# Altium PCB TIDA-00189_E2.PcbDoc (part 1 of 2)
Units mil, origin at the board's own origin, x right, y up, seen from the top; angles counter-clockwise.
Board outline 2350 x 1950 mil, 4 copper layers (Layer 1 - Top Layer, Layer 2 - GND, Layer 3 - Inner Layer, Layer 4 - Bottom Layer), stack 61.4 mil thick; 163 components, 96 nets, 412 pads, 169 vias.
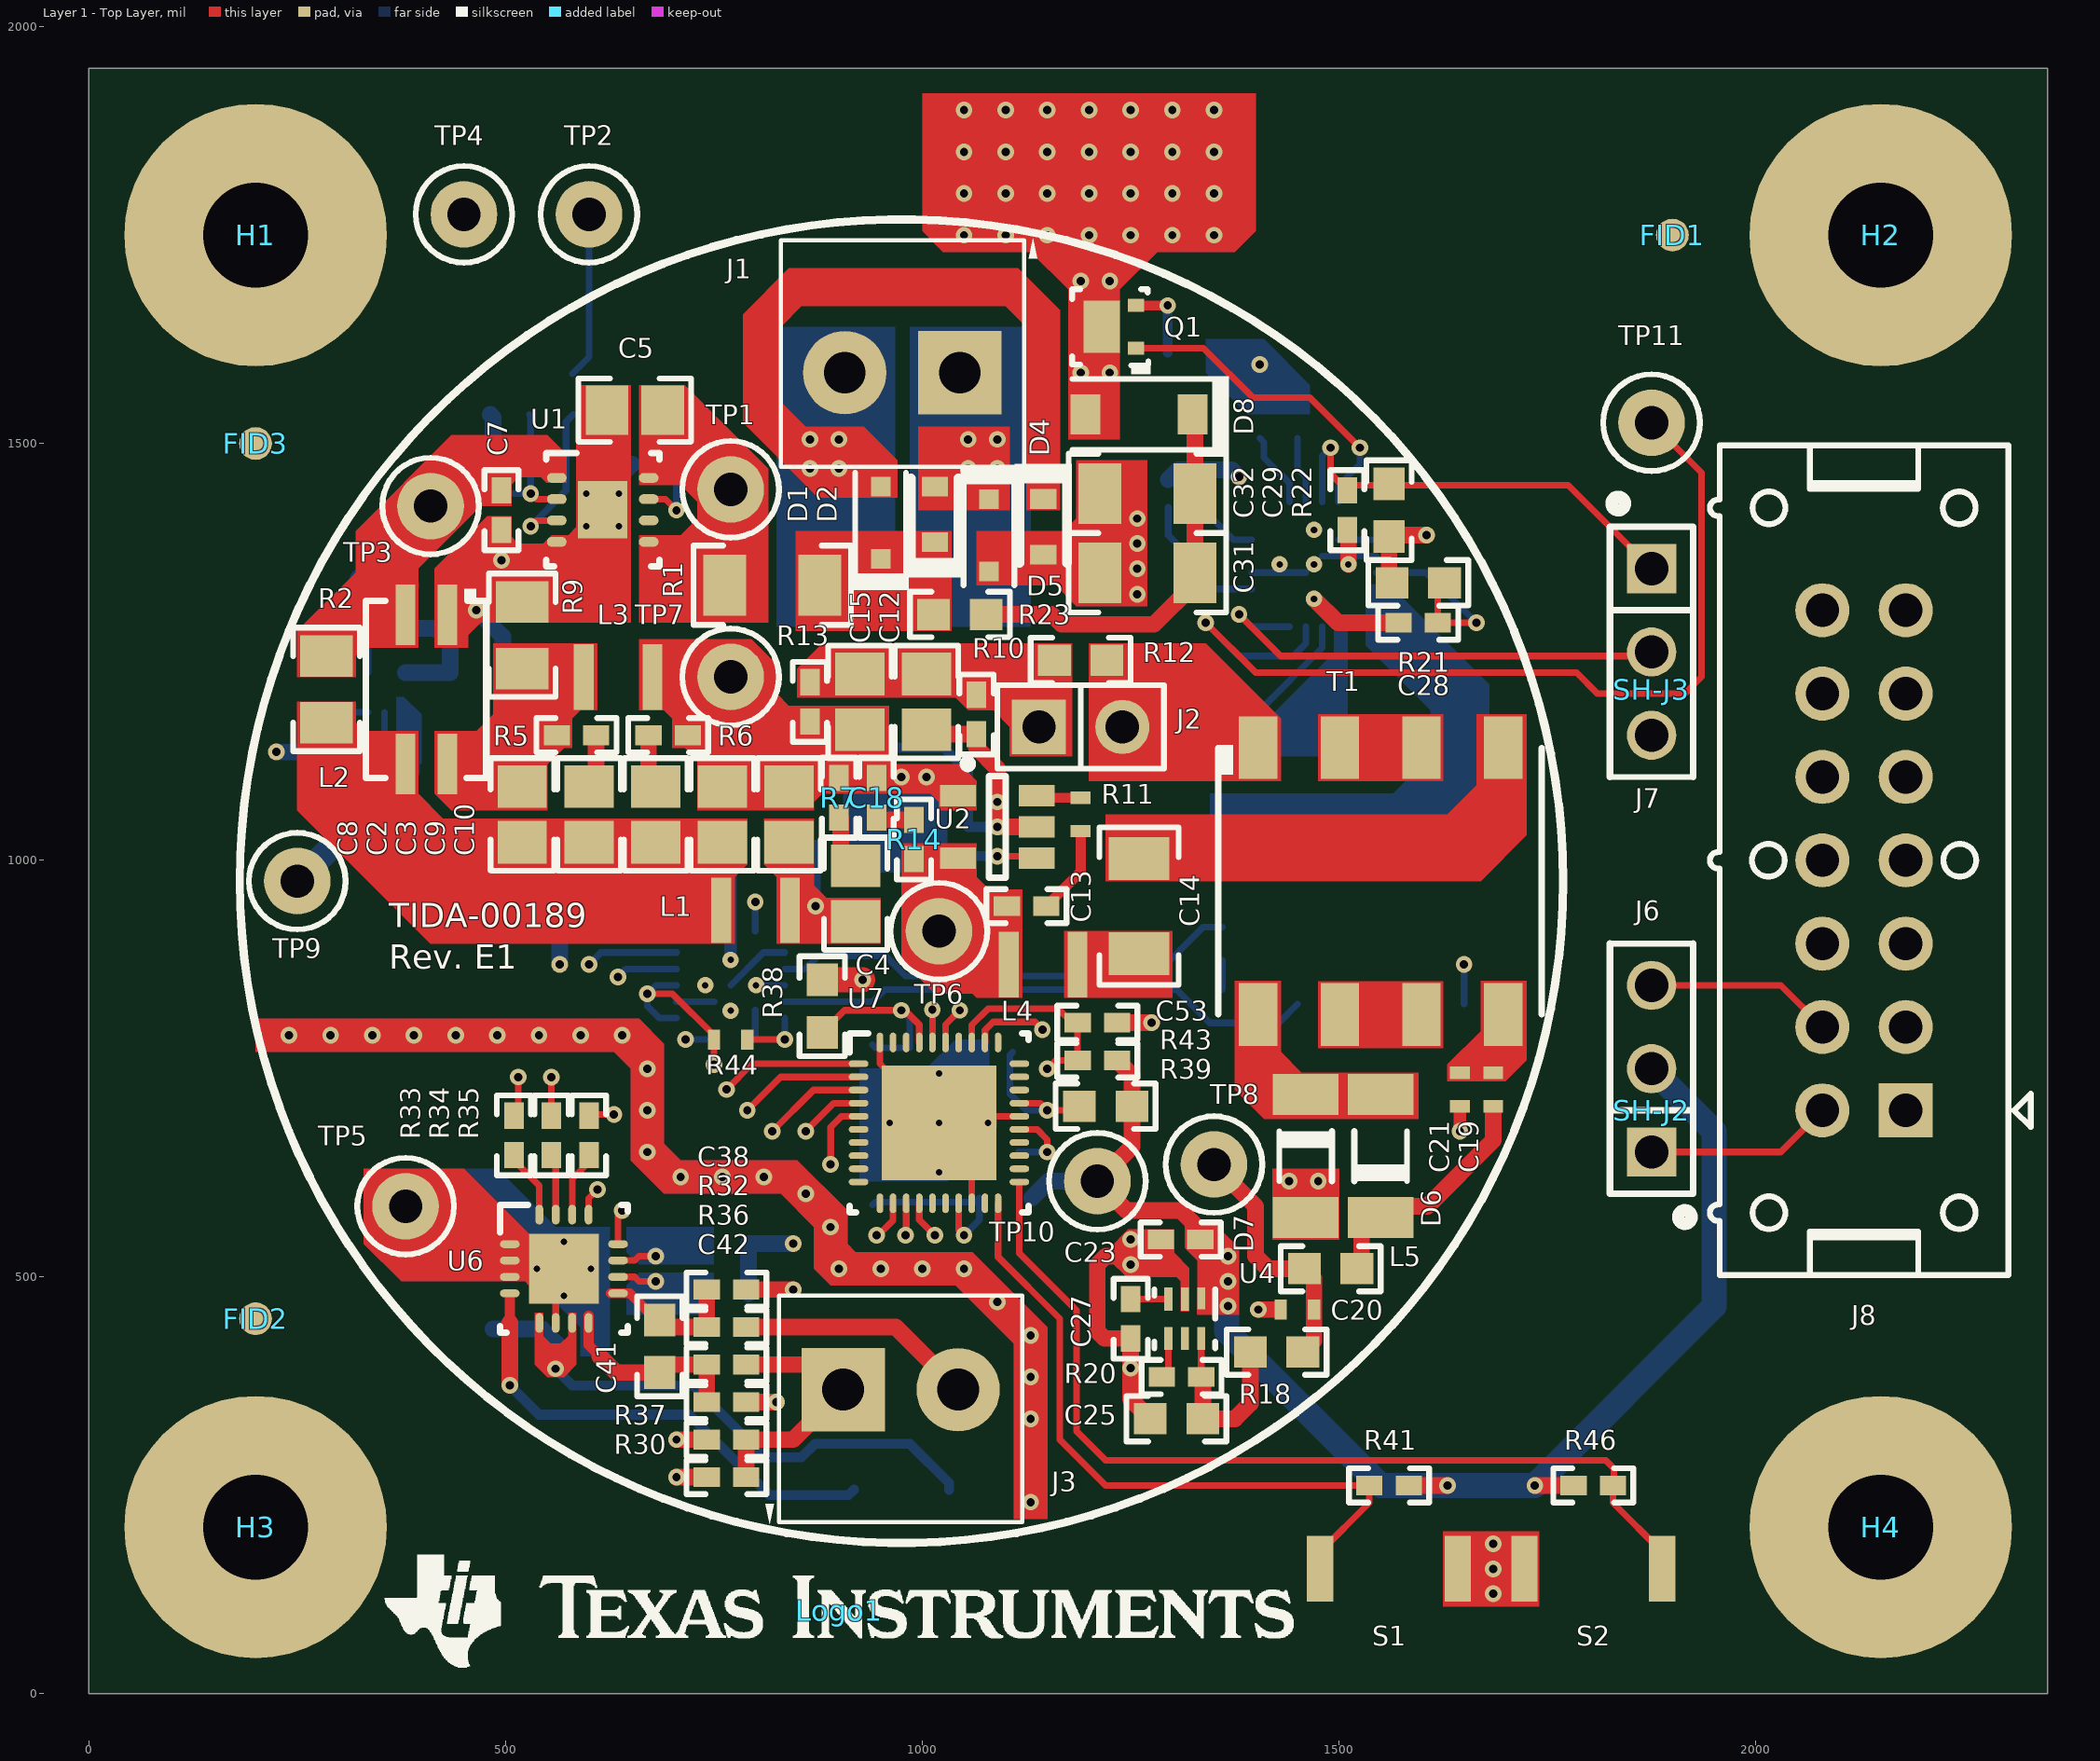
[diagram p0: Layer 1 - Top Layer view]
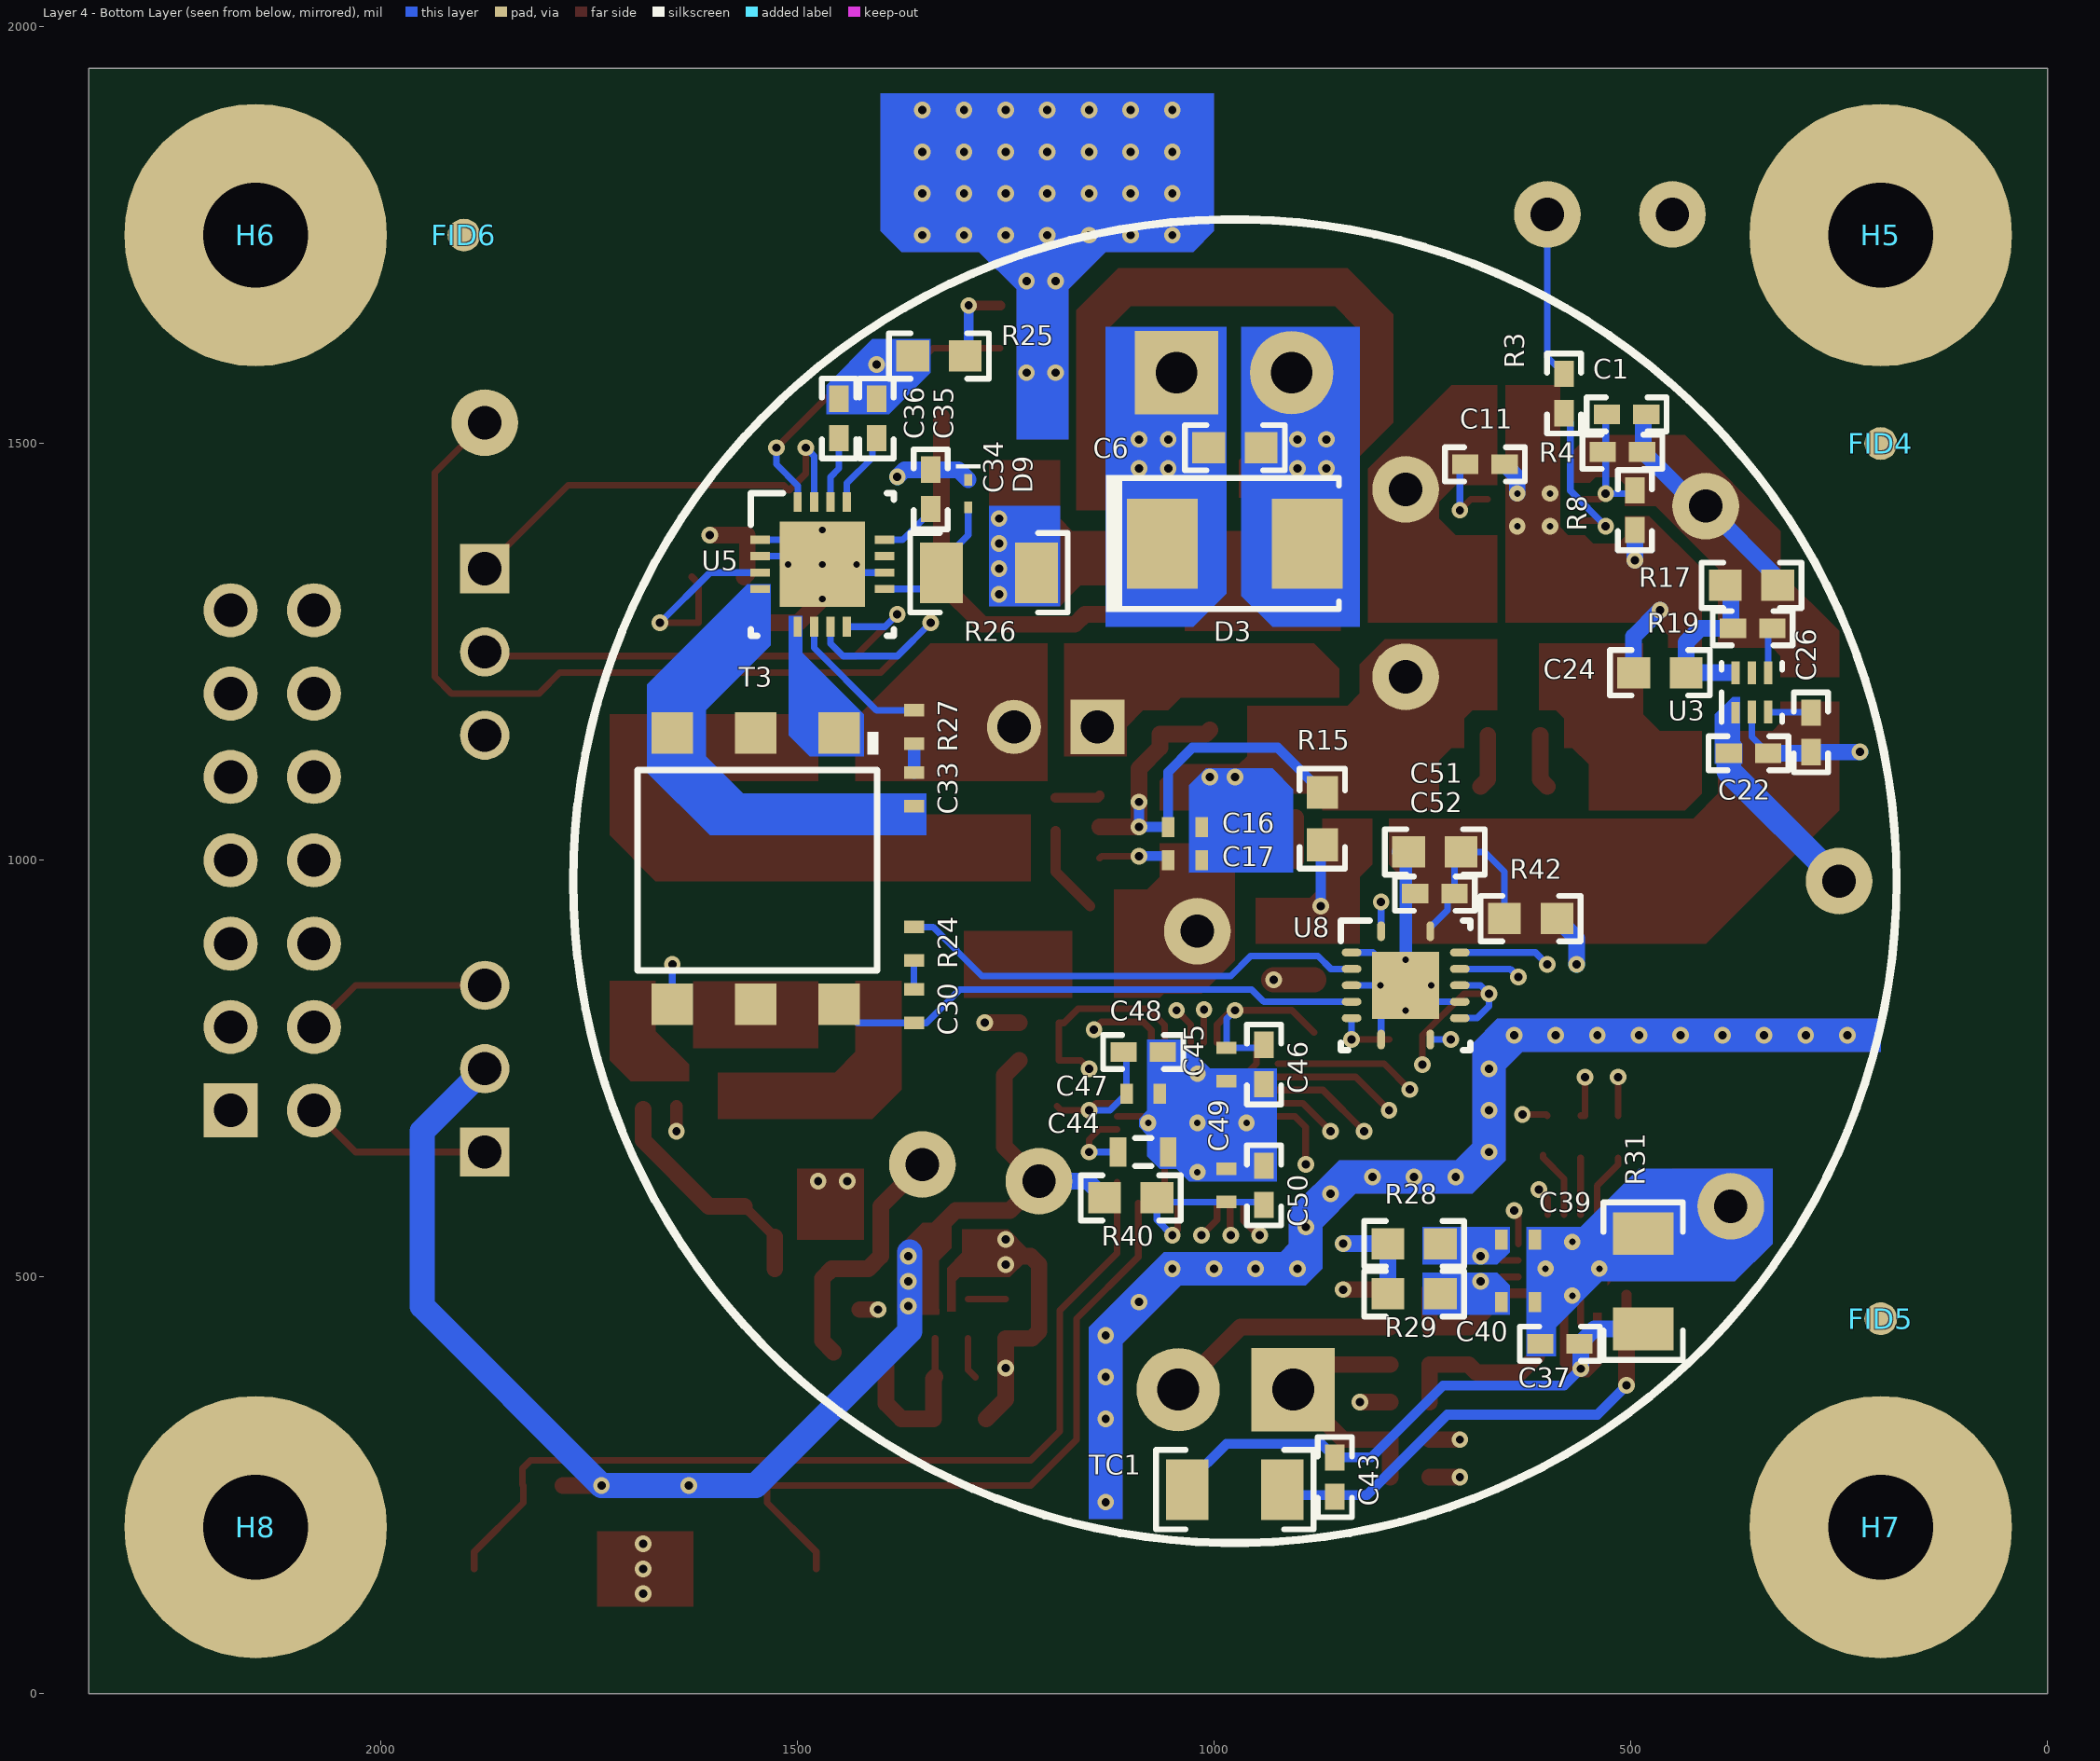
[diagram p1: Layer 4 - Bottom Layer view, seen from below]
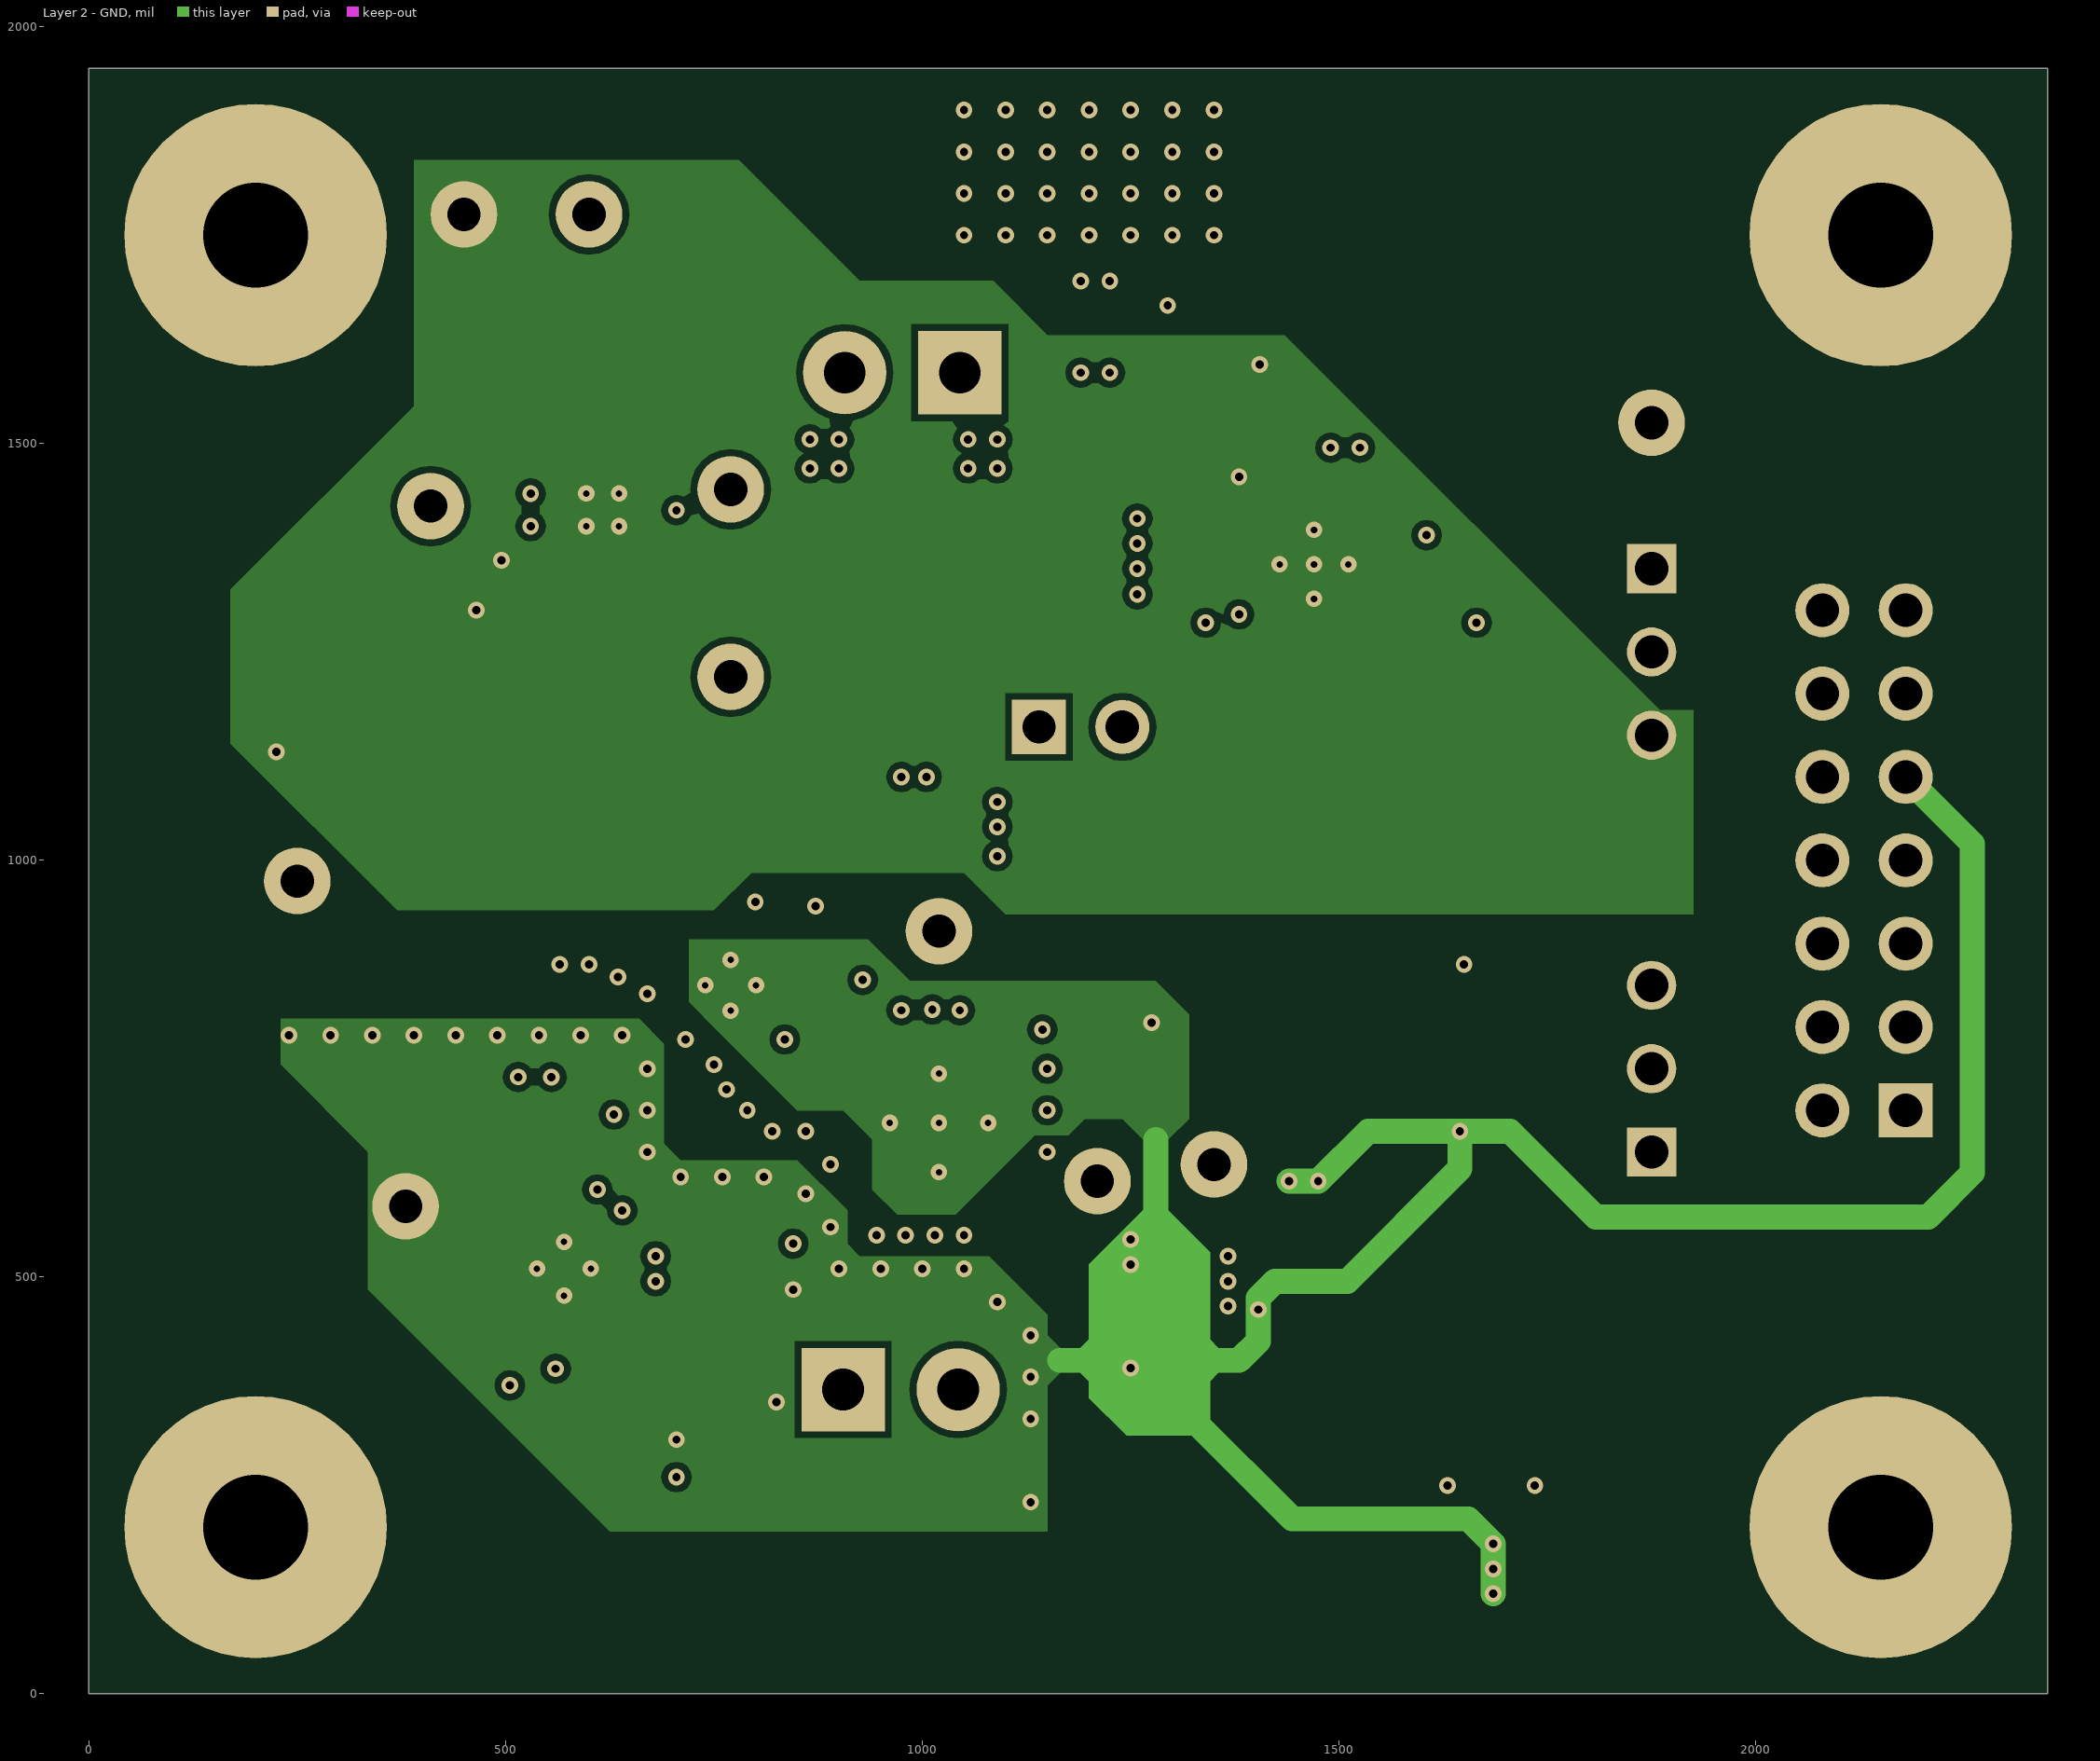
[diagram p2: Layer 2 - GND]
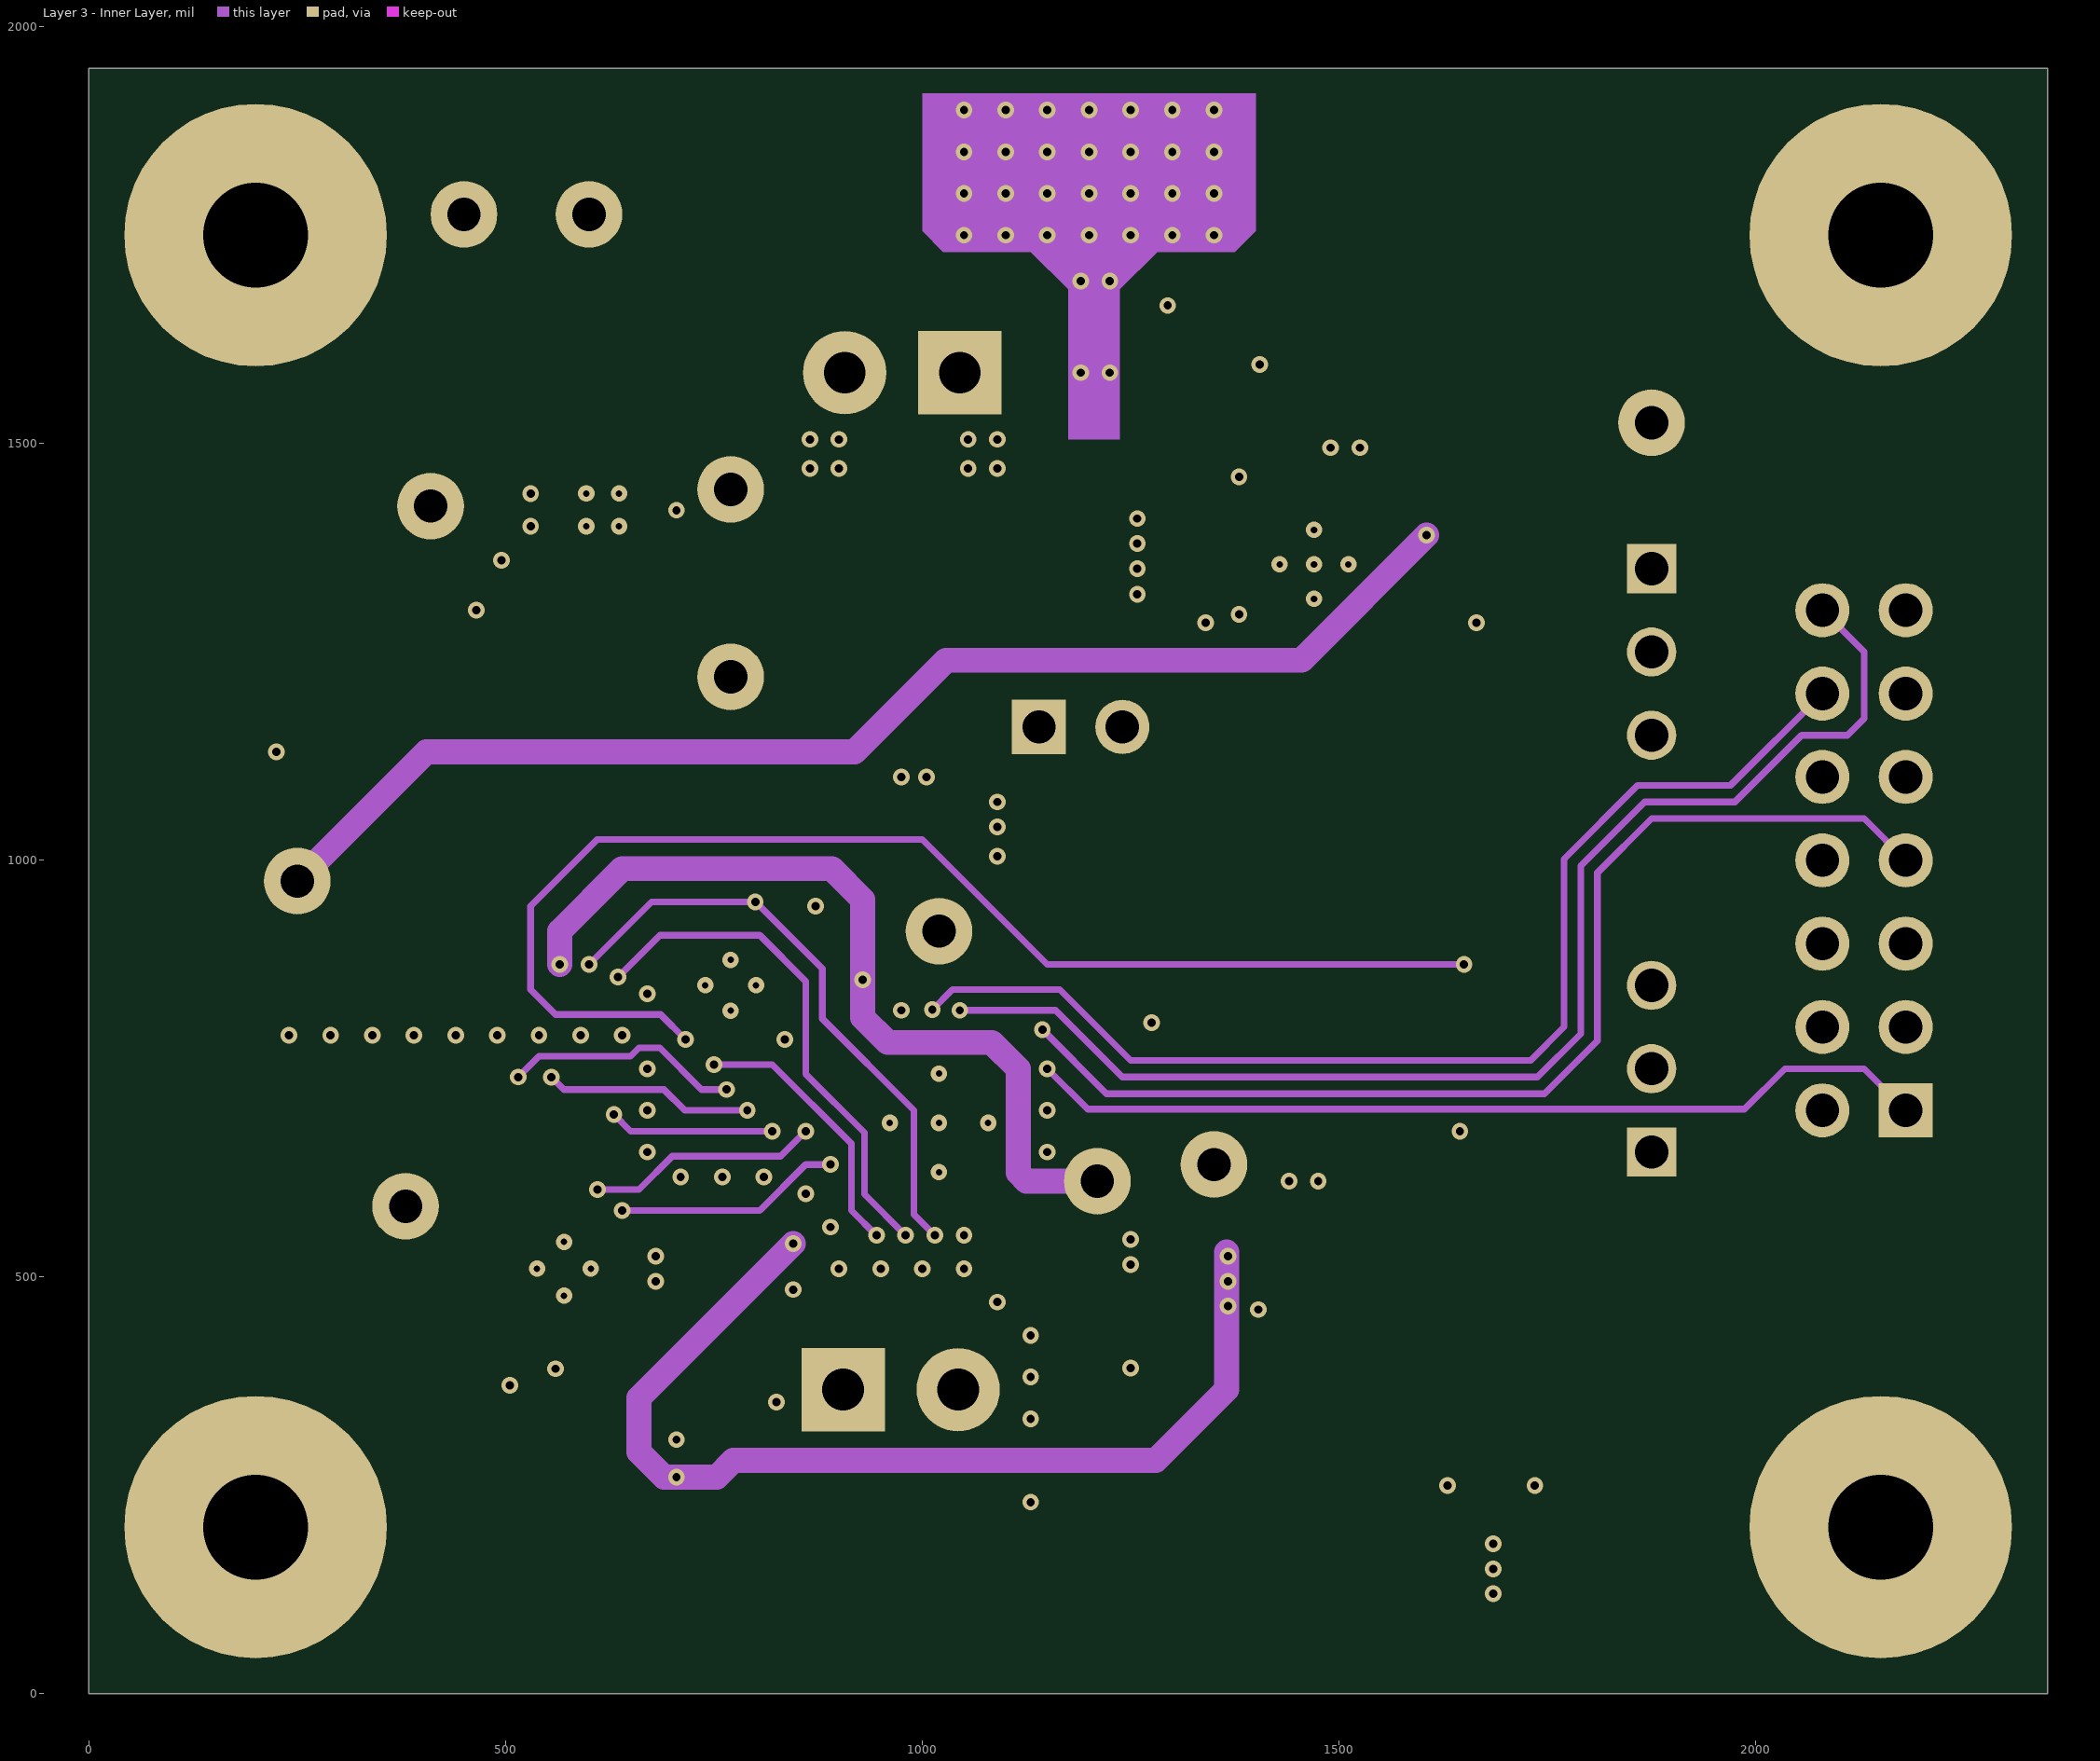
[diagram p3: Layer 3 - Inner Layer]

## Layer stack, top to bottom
Layer 1 - Top Layer: signal copper 1.4
Dielectric: core 18.6, 370HR, Dk 4.8
Layer 2 - GND: signal copper 1.4
Dielectric: prepreg 18.6, 370HR, Dk 4.8
Layer 3 - Inner Layer: signal copper 1.4
Dielectric: core 18.6, 370HR, Dk 4.8
Layer 4 - Bottom Layer: signal copper 1.4

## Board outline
0,0 0,1950 2350,1950 2350,0

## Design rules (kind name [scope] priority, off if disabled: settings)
AcuteAngle [All] p1: minimum=4.50000000000000E+0001 checktracksonly=FALSE
AssemblyTestPointUsage [All] p1: valid=2
Clearance Clearance_U7 [InComponent('U7')] p1: gap=7
Clearance Clearance_BoardEdge_MountingHoles [OnCopper and InComponentClass('Mounting Holes') vs IsKeepOut] p2: gap=40
Clearance Clearance_BoardEdge_Poly [OnCopper and InPoly vs IsKeepOut] p3: gap=25
Clearance Clearance_BoardEdge [OnCopper and Not InComponentClass('Logo') and not InComponentClass('FiducialMark') and not InRegion(1000,500,4000,800) and Not IsKeepout vs IsKeepOut] p4: gap=75
Clearance Clearance_Poly [InPolygon] p5: gap=8
Clearance [All] p6: gap=7.5
ComponentClearance ComponentClearance_Shunt [InComponentClass('Header') vs InComponentClass('Shunt')] p1 off: gap=0 collisioncheckmode=3 verticalgap=0 showdistances=FALSE
ComponentClearance ComponentClearance_Logo [InComponentClass('Logo')] p2 off: gap=50 collisioncheckmode=3 verticalgap=10 showdistances=FALSE
ComponentClearance ComponentClearance_ScrewToNut [(HasFootprint('NY PMS 440 0025 PH')) vs (HasFootprint('Keystone_1902C'))] p3 off: gap=5 collisioncheckmode=3 verticalgap=10 showdistances=FALSE
ComponentClearance ComponentClearance_MountingHoles [InComponentClass('Mounting Holes')] p4 off: gap=250 collisioncheckmode=3 verticalgap=100000 showdistances=FALSE
ComponentClearance ComponentClearance_SmallPassives [HasFootprint('0201*') or HasFootprint('0402*') or HasFootprint('0508') or HasFootprint('0603*') or HasFootprint('0612') or HasFootprint('0805*') or HasFootprint('0815*') or HasFootprint('0830*') or HasFootprint('1206*') or HasFootprint('1210*') or HasFootprint('1808*') or HasFootprint('1812*') or HasFootprint('1825*') or HasFootprint('2010*') or HasFootprint('2220*') or HasFootprint('2225*') or HasFootprint('2512*') or HasFootprint('2728*') or HasFootprint('3518*') vs HasFootprint('0201*') or HasFootprint('0402*') or HasFootprint('0508') or HasFootprint('0603*') or HasFootprint('0612') or HasFootprint('0805*') or HasFootprint('0815*') or HasFootprint('0830*') or HasFootprint('1206*') or HasFootprint('1210*') or HasFootprint('1808*') or HasFootprint('1812*') or HasFootprint('1825*') or HasFootprint('2010*') or HasFootprint('2220*') or HasFootprint('2225*') or HasFootprint('2512*') or HasFootprint('2728*') or HasFootprint('3518*')] p5 off: gap=20 collisioncheckmode=3 verticalgap=10 showdistances=FALSE
ComponentClearance ComponentClearance_THtoSMT [IsThruComponent vs IsSMTComponent] p6 off: gap=100 collisioncheckmode=3 verticalgap=30 showdistances=FALSE
ComponentClearance ComponentClearance_THtoTH [IsThruComponent vs IsThruComponent] p7 off: gap=118.11 collisioncheckmode=3 verticalgap=30 showdistances=FALSE
ComponentClearance [All] p8 off: gap=40 collisioncheckmode=3 verticalgap=10 showdistances=FALSE
DiffPairsRouting [All] p1: maxlimit=100 minlimit=10 mostfreqgap=10 maxuncoupledlength=1000
FabricationTestPointUsage TestPointUsage [All] p1: valid=2 allowmultiple=FALSE
FabricationTestpoint Testpoint [All] p1: side=3 testpointundercomponent=TRUE minsize=40 maxsize=100 preferedsize=60 minholesize=0 maxholesize=40 preferedholesize=32 testpointgrid=1 allowsidetop=TRUE allowsidebottom=TRUE usegrid=TRUE gridtolerance=0.01
FanoutControl Fanout_LCC [IsLCC] p1: bgadir=Out bgaviamode=Centered fanoutstyle=Auto fanoutdirection=Alternating viagrid=1 // Fanout_LCC (Default Rule)
FanoutControl Fanout_BGA [IsBGA] p2: bgadir=Out bgaviamode=Centered fanoutstyle=Auto fanoutdirection=Alternating viagrid=1 // Fanout_BGA (Default Rule)
FanoutControl Fanout_Default [All] p4: bgadir=Out bgaviamode=Centered fanoutstyle=Auto fanoutdirection=Alternating viagrid=1 // Fanout_Default (Default Rule)
FanoutControl Fanout_Small [(CompPinCount < 5)] p5: bgadir=Out bgaviamode=Centered fanoutstyle=Auto fanoutdirection=OutThenIn viagrid=1 // Fanout_Small (Default Rule)
HoleSize [All] p1: absolutevalues=TRUE maxlimit=251 minlimit=7.8 maxpercent=80.000 minpercent=20.000
MinimumAnnularRing MinimumAnnularRing_ThermalPadVias [IsVia and InAnyComponent] p1: minimumring=5.91
MinimumAnnularRing [All] p2: minimumring=5
MinimumSolderMaskSliver MinimumSolderMaskSliver_Logo [InComponentClass('Logo') vs InComponentClass('Logo')] p1: minsoldermaskwidth=0.7
MinimumSolderMaskSliver [All] p2: minsoldermaskwidth=3.94
PlaneConnect [All] p1: planeconnectstyle=Direct reliefexpansion=10 reliefentries=4 reliefconductorwidth=10 reliefairgap=10
PolygonConnect [All] p1: connectstyle=Direct reliefconductorwidth=10 reliefentries=4 polygonreliefangle="90 Angle" airgapwidth=10
RoutingVias ThermalPadVias [IsVia and InAnyComponent] p1: holewidth=7.87 width=19.68 viastyle="Through Hole" minholewidth=7.87 minwidth=19.68 maxholewidth=12.99 maxwidth=23.62
RoutingVias [All] p2: holewidth=16 width=34 viastyle="Through Hole" minholewidth=7.87 minwidth=20 maxholewidth=40 maxwidth=65
SMDToCorner [All] p1: distance=30000
SilkToSilkClearance [All] p1 off: silktosilkclearance=5
SilkscreenOverComponentPads [All] p1: minsilkscreentomaskgap=2
SolderMaskExpansion [All] p1: expansion=1.97
Width [All] p1: maxlimit=100 minlimit=6 preferedwidth=10 checkconnectedcopper=TRUE
14 further rules are at their usual default settings.

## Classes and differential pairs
component class TIDA-00189_E2_PWR: C1 C2 C3 C4 C5 C6 C7 C8 C9 C10 C11 C12 C13 C14 C15 C16 C17 C18 C19 C20 C21 C22 C23 C24 C25 C26 C27 D1 D2 D3 D4 D5 D6 D7 J1 J2 L1 L2 L3 L4 L5 R1 R2 R3 R4 R5 R6 R7 R8 R9 R10 R11 R12 R13 R14 R15 R17 R18 R19 R20 T1 TP1 TP2 TP3 TP4 TP5 TP6 TP7 TP8 TP9 TP10 U1 U2 U3 U4
component class TIDA-00189_E2_Periph: J6 J7 J8 R46 S2 SH-J2 SH-J3
component class TIDA-00189_E2_DAC: C28 C29 C30 C31 C32 C33 C34 C35 C36 D8 D9 Q1 R21 R22 R23 R24 R25 R26 R27 T3 TP11 U5
component class TIDA-00189_E2_AFE_MCU: C37 C38 C39 C40 C41 C42 C43 C44 C45 C46 C47 C48 C49 C50 C51 C52 C53 J3 R28 R29 R30 R31 R32 R33 R34 R35 R36 R37 R38 R39 R40 R41 R42 R43 R44 S1 TC1 U6 U7 U8
component class Shunt: SH-J2 SH-J3
component class "Mounting Holes": H1 H2 H3 H4
component class Logo: Logo1
component class TIDA-00189_E2_Hardware: FID1 FID2 FID3 FID4 FID5 FID6 H1 H2 H3 H4 H5 H6 H7 H8 Logo1 ZZ1 ZZ2 ZZ3 ZZ4
component class FiducialMark: FID1 FID2 FID3 FID4 FID5 FID6
component class AssemblyNote: ZZ1 ZZ2 ZZ3 ZZ4

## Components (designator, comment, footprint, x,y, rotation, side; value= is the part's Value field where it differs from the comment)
C1 "CAP, CERM, 0.01uF, 10V, +/-10%, X5R, 0402" 0402 505,1535 r0 bottom
C2 "GRM21BR71A106KE51L" 0805 600,1055 r90 top
C3 "GRM21BR71A106KE51L" 0805 680,1055 r90 top
C4 "GRM21BR71A106KE51L" 0805 920,960 r90 top
C5 "CAP, CERM, 0.47uF, 100V, +/-10%, X7R, 0805" 0805 655,1540 r180 top
C6 "CAP, CERM, 0.01uF, 100V, +/-10%, X7R, 0603" 0603 975,1495 r0 bottom locked
C7 "CAP, CERM, 2.2uF, 16V, +/-10%, X5R, 0402" 0402 495,1420 r270 top
C8 "CAP, CERM, 10uF, 10V, +/-10%, X7R, 0805" 0805 520,1055 r90 top
C9 "GRM21BR71A106KE51L" 0805 760,1055 r90 top
C10 "GRM21BR71A106KE51L" 0805 840,1055 r90 top
C11 "GRM155R61A104KA01D" 0402 675,1475 r180 bottom
C12 "CAP, CERM, 10uF, 10V, +/-10%, X7R, 0805" 0805 1005,1190 r90 top
C13 "CAP, CERM, 1uF, 10V, +/-10%, X5R, 0402" 0402 1125,945 r180 top
C14 "CAP, CERM, 22uF, 10V, +/-10%, X5R, 1206" 1206 1260,945 r270 top
C15 "CAP, CERM, 10uF, 10V, +/-10%, X7R, 0805" 0805 925,1190 r270 top
C16 "CAP, CERM, 4.7uF, 10V, +/-20%, X5R, 0402" 0402S 1035,1040 r180 bottom
C17 "CAP, CERM, 4.7uF, 10V, +/-20%, X5R, 0402" 0402S 1035,1000 r180 bottom
C18 "GRM155R71H561KA01D" 0402 945,1075 r90 top
C19 "CAP, CERM, 1uF, 10V, +/-10%, X5R, 0402" 0402S 1685,725 r90 top
C20 "CAP, CERM, 1uF, 10V, +/-10%, X5R, 0402" 0402S 1450,461 r180 top
C21 "CAP, CERM, 1uF, 10V, +/-10%, X5R, 0402" 0402S 1645,725 r270 top
C22 "CAP, CERM, 1uF, 10V, +/-10%, X5R, 0402" 0402 358.7,1128.38 r180 bottom
C23 "GRM155R61A105KE15D" 0402 1310,545 r180 top
C24 "GRM188R71A225KE15D" 0603 465,1225 r0 bottom
C25 "GRM188R71A225KE15D" 0603 1305,330 r180 top
C26 "CAP, CERM, 0.1uF, 6.3V, +/-10%, X7R, 0402" 0402 283.7,1153.38 r270 bottom
C27 "GRM155R70J104KA01D" 0402 1250,450 r270 top
C28 "GRM155R71C104KA88D" 0402 1595,1285 r180 top
C29 "GRM155R71C104KA88D" 0402 1510,1420 r270 top
C30 "GRM155R71C102KA01D" 0402S 1360,825 r90 bottom
C31 "12061C104JAT2A" 1206 1270,1345 r180 top
C32 "GRM31CR72A105KA01L" 1206 1270,1440 r180 top
C33 "GRM155R71C102KA01D" 0402S 1360,1085 r270 bottom
C34 "GRM155R70J222KA01D" 0402 1340,1445 r90 bottom
C35 "GRM155R70J222KA01D" 0402 1405,1530 r90 bottom
C36 "GRM155R70J222KA01D" 0402 1450,1530 r90 bottom
C37 "GRM155R61A105KE15D" 0402 585,420 r180 bottom
C38 "GRM155R60J274KE01D" 0402 765,485 r180 top
C39 "GRM155R60J224KE01D" 0402S 635,545 r180 bottom
C40 "GRM155R60J224KE01D" 0402S 635,470 r180 bottom
C41 "GRM188R60J475KE19D" 0603 685,417 r270 top
C42 "GRM155R60J274KE01D" 0402 765,350 r0 top
C43 "GRM155R61A105KE15D" 0402 855,260 r270 bottom
C44 "GRM188R70J474KA01D" 0603S 1085,650 r180 bottom
C45 "GRM155R70J104KA01D" 0402S 985,755 r270 bottom
C46 "CL05A106MQ5NUNC" 0402 940,755 r270 bottom
C47 "GRM155R70J104KA01D" 0402S 1085,720 r180 bottom
C48 "CL05A106MQ5NUNC" 0402 1085,770 r180 bottom
C49 "GRM155R70J104KA01D" 0402S 985,610 r90 bottom
C50 "CL05A106MQ5NUNC" 0402 940,610 r90 bottom
C51 "GRM188R61A335KE15D" 0603 735,1010 r0 bottom
C52 "GRM155R61A104KA01D" 0402 735,960 r0 bottom
C53 "GRM155R70J222KA01D" 0402 1210,805 r0 top
D1 "BAT46WJ,115" SOD-323F 950,1405 r90 top
D2 "CDSU101A" SOD-523F 1015,1415 r90 top
D3 "SM6T39CA" SMB 975,1380 r180 bottom locked
D4 "CDSU101A" SOD-523F 1145,1400 r270 top
D5 "BAT46WJ,115" SOD-323F 1080,1390 r270 top
D6 "PMLL4153,115" SOD-80 1550,645 r90 top
D7 "PMLL4153,115" SOD-80 1460,645 r270 top
D8 "MMSZ4686T1G" SOD-123 1260,1535 r180 top
D9 "ESD9R3.3ST5G" ESD9R3.3ST5G 1295,1440 r270 bottom
FID1 "Fiducial" Fiducial10-30 1900,1750 r0 top
FID2 "Fiducial" Fiducial10-30 200,450 r0 top
FID3 "Fiducial" Fiducial10-30 200,1500 r0 top
FID4 "Fiducial" Fiducial10-30 200,1500 r180 bottom
FID5 "Fiducial" Fiducial10-30 200,450 r180 bottom
FID6 "Fiducial" Fiducial10-30 1900,1750 r180 bottom
H1 "NY PMS 440 0025 PH" "NY PMS 440 0025 PH" 200,1750 r0 top locked
H2 "NY PMS 440 0025 PH" "NY PMS 440 0025 PH" 2150,1750 r0 top locked
H3 "NY PMS 440 0025 PH" "NY PMS 440 0025 PH" 200,200 r0 top locked
H4 "NY PMS 440 0025 PH" "NY PMS 440 0025 PH" 2150,200 r0 top locked
H5 "1902C" Keystone_1902C 200,1750 r180 bottom locked
H6 "1902C" Keystone_1902C 2150,1750 r180 bottom locked
H7 "1902C" Keystone_1902C 200,200 r180 bottom locked
H8 "1902C" Keystone_1902C 2150,200 r180 bottom locked
J1 "ED555/2DS" TERM_BLK_ED555-2DS 1045,1585 r180 top locked
J2 "90120-0122" CONN_90120-0122 1190,1160 r0 top
J3 "ED555/2DS" TERM_BLK_ED555-2DS 905,365 r0 top locked
J6 "PEC03SAAN" CONN_PEC03SAAN 1875,750 r90 top
J7 "PEC03SAAN" CONN_PEC03SAAN 1875,1250 r270 top
J8 "SBH11-PBPC-D07-ST-BK" CONN_SBH11-PBPC-D07-ST-BK 2130,1000 r90 top
L1 "CB2518T470K" IND_CB2518 800,940 r0 top
L2 "DR221-474AE" Bourns_DR221 405,1205 r270 top
L3 "CB2518T470K" IND_CB2518 635,1220 r0 top
L4 "CB2518T330K" IND_CB2518 1145,875 r0 top
L5 "BLM18HG601SN1D" 0603 1490,510 r180 top
Logo1 "Texas Instruments" TI_Horizontal_Overlay_Small 900,100 r0 top
Q1 "BC56-16PA,115" SOT1061 1225,1640 r180 top
R1 "CRCW1206200RFKEA" 1206 820,1330 r180 top
R2 "CRCW08050000Z0EA" 0805_HV 285,1205 r270 top
R3 "CRCW0402100KFKED" 0402 580,1560 r90 bottom
R4 "RES, 698k ohm, 1%, 0.063W, 0402" 0402 510,1490 r180 bottom
R5 "RES, 200 ohm, 1%, 0.063W, 0402" 0402 585,1150 r0 top
R6 "CRCW0402200RFKED" 0402 695,1150 r180 top
R7 "CRCW0402200RFKED" 0402 900,1075 r270 top
R8 "RES, 237k ohm, 1%, 0.063W, 0402" 0402 495,1420 r90 bottom
R9 "CRCW08050000Z0EA" 0805_HV 520,1270 r270 top
R10 "RES, 499k ohm, 1%, 0.063W, 0402" 0402 1065,1175 r270 top
R11 "RES, 1.00k ohm, 1%, 0.063W, 0402" 0402S 1190,1055 r270 top
R12 "CRCW06030000Z0EA" 0603 1190,1240 r180 top
R13 "RES, 499k ohm, 1%, 0.063W, 0402" 0402 865,1190 r90 top
R14 "RES, 10.0 ohm, 1%, 0.063W, 0402" 0402 990,1025 r270 top
R15 "CRCW060310R0FKEA" 0603 870,1050 r90 bottom
R17 "CRCW060310R0FKEA" 0603 355,1330 r0 bottom
R18 "CRCW060310R0FKEA" 0603 1425,410 r180 top
R19 "RES, 0 ohm, 5%, 0.063W, 0402" 0402 353.7,1278.38 r0 bottom
R20 "CRCW04020000Z0ED" 0402 1311,380 r0 top
R21 "CRCW060310R0FKEA" 0603 1595,1333 r180 top
R22 "CRCW060310R0FKEA" 0603 1560,1420 r270 top
R23 "RT0603BRD07100RL" 0603 1045,1295 r180 top
R24 "CRCW040240R2FKED" 0402S 1360,900 r270 bottom
R25 "CRCW060320R0FKEA" 0603 1330,1605 r180 bottom
R26 "CRCW12060000Z0EA" 1206 1270,1345 r180 bottom
R27 "CRCW040240R2FKED" 0402S 1360,1160 r90 bottom
R28 "CRCW060310R0FKEA" 0603 760,540 r0 bottom
R29 "CRCW060310R0FKEA" 0603 760,480 r0 bottom
R30 "CRCW04022M00FKED" 0402 765,260 r180 top
R31 "PFC-W1206R-12-3241-B" 1206 485,495 r90 bottom
R32 "CRCW04021K00FKED" 0402 765,440 r180 top
R33 "CRCW040247R0JNED" 0402 510,670 r90 top
R34 "CRCW040247R0JNED" 0402 555,670 r90 top
R35 "CRCW040247R0JNED" 0402 600,670 r90 top
R36 "CRCW04021K00FKED" 0402 765,395 r180 top
R37 "CRCW04022M00FKED" 0402 765,305 r0 top
R38 "CRCW060310R0FKEA" 0603 880,825 r90 top
R39 "CRCW060310R0FKEA" 0603 1220,705 r0 top
R40 "CRCW060310R0FKEA" 0603 1100,595 r0 bottom
R41 "CRCW04021M00JNED" 0402 1560,250 r0 top
R42 "CRCW060310R0FKEA" 0603 620,930 r0 bottom
R43 "CRCW040247K0JNED" 0402 1210,760 r0 top
R44 "CRCW04022K00FKED" 0402S 770,785 r180 top
R46 "CRCW04021M00JNED" 0402 1805,250 r180 top
S1 "SKRKAEE010" SW_SKRKAEE010 1560,150 r180 top
S2 "SKRKAEE010" SW_SKRKAEE010 1805,150 r0 top
SH-J2 "969102-0000-DA" SNT-100-BK-G 1875,700 r90 top
SH-J3 "969102-0000-DA" SNT-100-BK-G 1875,1205 r270 top
T1 "750314839" Wurth_750314445 1550,975 r0 top
T3 "S5394-CLB" Coilcraft_S5394-CL 1550,990 r270 bottom
TC1 "PTS120601B100RP100" 1206 975,245 r0 bottom
TP1 "5000" Keystone5000 770,1445 r270 top
TP2 "5002" Keystone5002 600,1775 r270 top
TP3 "5000" Keystone5000 410,1425 r270 top
TP4 "5001" Keystone5001 450,1775 r90 top
TP5 "5001" Keystone5001 380,585 r0 top
TP6 "5002" Keystone5002 1020,915 r0 top
TP7 "5001" Keystone5001 770,1220 r0 top
TP8 "5000" Keystone5000 1350,635 r0 top
TP9 "5000" Keystone5000 250,975 r0 top
TP10 "5000" Keystone5000 1210,615 r0 top
TP11 "5002" Keystone5002 1875,1525 r0 top
U1 "TPS7A1601DRB" DRB0008A 616.48,1420.45 r0 top
U2 "TPS60402DBV" DBV0005A_N 1090,1040 r180 top
U3 "TPS71733DSE" DSE0006A 354.7,1201.38 r90 bottom
U4 "TPS71733DSE" DSE0006A 1315,450 r270 top
U5 "DAC161P997CISQ/NOPB" RGH0016A 1470,1355 r180 bottom
U6 "ADS1220IRVA" RVA0016A 570,510 r0 top
U7 "MSP430F5172IRSB" RSB0040B 1020,685 r0 top
U8 "SN74LVC125ARGY" RGY0014A 770,850 r180 bottom
ZZ1 "This Assembly Note is for PCB labels only" AssemblyNoteLabel 185,3938 r0 top
ZZ2 "This Assembly Note will show in the PcbDoc and associated outputs" AssemblyNote 185,3829.11 r0 top
ZZ3 "This Assembly Note will show in the PcbDoc and associated outputs" AssemblyNote 185,3740.56 r0 top
ZZ4 "This Assembly Note will show in the PcbDoc and associated outputs" AssemblyNote 185,3652 r0 top

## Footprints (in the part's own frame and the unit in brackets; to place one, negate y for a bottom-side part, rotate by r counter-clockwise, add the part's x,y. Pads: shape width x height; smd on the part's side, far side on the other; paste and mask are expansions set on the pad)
0402 [mm] "0402 from SM-752 data"
  rect 0.8x0.6 smd: 1(-0.6,0) 2(0.6,0)
  silkscreen extent -1.22,-0.52 1.22,0.52, body extent -0.55,-0.3 0.55,0.3, height 0.6
0402S [mil] "Based on C0402S footprint from PADS legacy"
  rect 15x24 smd: 1(-20,0) 2(20,0)
  body extent -22,-12 22,12, height 24
0603 [mm] "0603 from SM-752 data"
  rect 1x0.95 smd: 1(-0.8,0) 2(0.8,0)
  silkscreen extent -1.52,-0.69 1.52,0.69, body extent -0.87,-0.47 0.87,0.47, height 0.85
0603S [mil]
  rect 20x35 smd: 1(-30,0) 2(30,0)
  silkscreen extent -10,-17 10,17, body extent -34,-19 34,19, height 33
0805 [mm] "0805 from SM-752 data"
  rect 1.3x1.5 smd: 1(-0.85,0) 2(0.85,0)
  silkscreen extent -1.72,-0.97 1.72,0.97, body extent -1.1,-0.72 1.1,0.72, height 1.1
0805_HV [mil] "0805 with 30mil clearance between pads"
  rect 50x63 smd: 1(-40,0) 2(40,0)
  silkscreen extent -74,-40 74,40, body extent -43,-29 43,29, height 43
1206 [mm] "1206 from SM-752 data"
  rect 1.3x1.85 smd: 1(-1.45,0) 2(1.45,0)
  silkscreen extent -2.4,-1.21 2.4,1.21, body extent -1.7,-0.9 1.7,0.9, height 1.35
AssemblyNote [mil] "Assembly Note"
AssemblyNoteLabel [mil] "Assembly Note for PCB Labels"
Bourns_DR221 [mm] "BOURNS"
  rect 1.85x0.6 smd: 1(-2.275,0.635) 2(-2.275,-0.635) 3(2.275,-0.635) 4(2.275,0.635)
  silkscreen extent -3.07,-1.85 2.7,1.83, body extent -3.15,-1.8 3.15,1.8, height 3.51
Coilcraft_S5394-CL [mm] "COILCRAFT"
  rect 1.27x1.27 smd: 1(-4.13,2.54) 2(-4.13,0) 3(-4.13,-2.54) 4(4.13,-2.54) 5(4.13,0) 6(4.13,2.54)
  silkscreen extent -4.18,-3.6 3.1,3.75, body extent -4.25,-3.45 4.25,3.54, height 5.21
CONN_90120-0122 [mm] "Molex"
  rect 1.65x1.65 hole 1.016 mask+0: 1(-1.27,0)
  round 1.65 hole 1.016 mask+0: 2(1.27,0)
  silkscreen extent -3.56,-1.27 2.54,1.27, body extent -2.54,-1.27 2.54,1.27, height 9.29
CONN_PEC03SAAN [mm] "SULLINS"
  rect 1.5x1.5 hole 1.016: 1(-2.54,0)
  round 1.5 hole 1.016: 2(0,0) 3(2.54,0)
  silkscreen extent -4.72,-1.27 3.81,1.27, body extent -3.84,-1.3 3.84,1.3, height 8.38
CONN_SBH11-PBPC-D07-ST-BK [mm] "Sullins recommended land pattern"
  rect 1.65x1.65 hole 1.016 mask+0: 1(-7.62,-1.27)
  round 1.65 hole 1.016 mask+0: 2(-7.62,1.27) 3(-5.08,-1.27) 4(-5.08,1.27) 5(-2.54,-1.27) 6(-2.54,1.27) 7(0,-1.27) 8(0,1.27) 9(2.54,-1.27) 10(2.54,1.27) 11(5.08,-1.27) 12(5.08,1.27) 13(7.62,-1.27) 14(7.62,1.27)
  silkscreen extent -12.64,-5.08 12.64,4.7, body extent -12.64,-4.4 12.64,4.7, height 9.12
DBV0005A_N [mm] "SOT23, 5-Leads, Body 2.9x1.6mm, Pitch 0.95mm, Lead Span 2.8mm, IPC Medium Density"
  rect 1.1x0.65 smd: 1(-1.2,0.95) 2(-1.2,0) 3(-1.2,-0.95) 4(1.2,-0.95) 5(1.2,0.95)
  silkscreen extent -0.25,-1.55 0.25,1.55, body extent -1.42,-1.46 1.42,1.46, height 1.08
DRB0008A [mm] "SON, 8-Leads, Body 3x3mm, Pitch 0.65mm, Thermal Pad 1.75x1.5mm, TI Recommended"
  oval 0.6x0.3 smd: 1(-1.4,0.975) 2(-1.4,0.325) 3(-1.4,-0.325) 4(-1.4,-0.975) 5(1.4,-0.975) 6(1.4,-0.325) 7(1.4,0.325) 8(1.4,0.975)
  rect 1.5x1.75 smd paste-0.75: 9(0,0)
  Layer 1 - Top Layer region: -0.465,-1.5 -0.465,-0.875 -0.75,-0.875 -0.75,0.875 -0.465,0.875 -0.465,1.5 -0.185,1.5 -0.185,0.875 0.185,0.875 0.185,1.5 0.465,1.5 0.465,0.875 0.75,0.875 0.75,-0.875 0.465,-0.875 0.465,-1.5 0.185,-1.5 0.185,-0.875 -0.185,-0.875 -0.185,-1.5
  silkscreen extent -1.73,-1.73 1.73,1.73, body extent -1.57,-1.57 1.58,1.58, height 1.01
DSE0006A [mm] "TI recommended land pattern"
  rect 0.66x0.25 smd: 1(-0.62,0.5)
  rect 0.7x0.25 smd: 2(-0.6,0) 3(-0.6,-0.5) 4(0.6,-0.5) 5(0.6,0) 6(0.6,0.5)
  Layer 1 - Top Layer region: -0.3,0.625 -0.25,0.625 -0.15,0.525 -0.15,0.375 -0.3,0.375
  silkscreen extent -0.9,-0.92 0.9,0.92, body extent -0.77,-0.77 0.77,0.77, height 0.8
ESD9R3.3ST5G [mm] "TVS DIODE 3.3VWM 7.8VC SOD923"
  rect 0.36x0.25 smd: 1(-0.42,0) 2(0.42,0)
  silkscreen extent -0.89,-0.38 -0.76,0.38, body extent -0.45,-0.35 0.45,0.35, height 0.4
Fiducial10-30 [mm]
  round 1 smd paste-0.5 mask+1: 1(0,0)
IND_CB2518 [mm] "TAIYO YUDEN"
  rect 0.6x2 smd: 1(-1.05,0) 2(1.05,0)
  body extent -1.35,-1 1.35,1, height 2
Keystone5000 [mil] "For Keystone 500x miniature loop terminals"
  round 80 hole 40: 1(0,0)
  silkscreen extent -58,-58 58,58, body extent -49,-49 49,49, height 182
Keystone5001 [mil] "For Keystone 500x miniature loop terminals"
  round 80 hole 40: 1(0,0)
  silkscreen extent -58,-58 58,58, body extent -49,-49 49,49, height 182
Keystone5002 [mil] "For Keystone 500x miniature loop terminals"
  round 80 hole 40: 1(0,0)
  silkscreen extent -58,-58 58,58, body extent -49,-49 49,49, height 182
Keystone_1902C [mil] "Hex Standoff, 4-40 threaded, nylon"
  body extent -145,-126 146,126, height 501
"NY PMS 440 0025 PH" [mm] "4-40 nylon screw and mounting hole"
  round 8 hole 3.2: 1(0,0)
  body extent -3.3,-3.3 3.3,3.3, height 2.69
RGH0016A [mm] "QFN, 16-Leads, Body 4x4mm, Pitch 0.5mm, TI Recommended"
  rect 0.6x0.25 smd: 1(-1.9,0.75) 2(-1.9,0.25) 3(-1.9,-0.25) 4(-1.9,-0.75) 9(1.9,-0.75) 10(1.9,-0.25) 11(1.9,0.25) 12(1.9,0.75)
  rect 0.25x0.6 smd: 5(-0.75,-1.9) 6(-0.25,-1.9) 7(0.25,-1.9) 8(0.75,-1.9) 13(0.75,1.9) 14(0.25,1.9) 15(-0.25,1.9) 16(-0.75,1.9)
  rect 2.6x2.6 smd paste-1.3: 17(0,0)
  silkscreen extent -2.17,-2.17 2.17,2.17, body extent -2.05,-2.05 2.05,2.05, height 0.81
RGY0014A [mm] "QFN, 14-Leads, Body 3.5x3.5mm, Pitch 0.5mm, Thermal Pad 2.05x2.05mm, TI Recommended"
  oval 0.24x0.6 smd: 1(-0.75,1.65) 7(-0.75,-1.65) 8(0.75,-1.65) 14(0.75,1.65)
  oval 0.6x0.24 smd: 2(-1.65,1) 3(-1.65,0.5) 4(-1.65,0) 5(-1.65,-0.5) 6(-1.65,-1) 9(1.65,-1) 10(1.65,-0.5) 11(1.65,0) 12(1.65,0.5) 13(1.65,1)
  rect 2.05x2.05 smd paste-1.025: 15(0,0)
  silkscreen extent -1.98,-1.97 1.98,1.97, body extent -1.83,-1.83 1.82,1.82, height 1.01
RSB0040B [mm] "QFN, 40-Leads, Body 5x5mm, Pitch 0.4mm, Thermal Pad 3.5x3.5mm, TI Recommended"
  oval 0.6x0.2 smd: 1(-2.45,1.8) 2(-2.45,1.4) 3(-2.45,1) 4(-2.45,0.6) 5(-2.45,0.2) 6(-2.45,-0.2) 7(-2.45,-0.6) 8(-2.45,-1) 9(-2.45,-1.4) 10(-2.45,-1.8) 21(2.45,-1.8) 22(2.45,-1.4) 23(2.45,-1) 24(2.45,-0.6) 25(2.45,-0.2) 26(2.45,0.2) 27(2.45,0.6) 28(2.45,1) 29(2.45,1.4) 30(2.45,1.8)
  oval 0.2x0.6 smd: 11(-1.8,-2.45) 12(-1.4,-2.45) 13(-1,-2.45) 14(-0.6,-2.45) 15(-0.2,-2.45) 16(0.2,-2.45) 17(0.6,-2.45) 18(1,-2.45) 19(1.4,-2.45) 20(1.8,-2.45) 31(1.8,2.45) 32(1.4,2.45) 33(1,2.45) 34(0.6,2.45) 35(0.2,2.45) 36(-0.2,2.45) 37(-0.6,2.45) 38(-1,2.45) 39(-1.4,2.45) 40(-1.8,2.45)
  rect 3.5x3.5 smd paste-1.75: 41(0,0)
  silkscreen extent -2.72,-2.73 2.72,2.73, body extent -2.57,-2.57 2.58,2.58, height 0.81
RVA0016A [mm] "QFN, 16-Leads, Body 3.5x3.5mm, Pitch 0.5mm, Thermal Pad 2.14x2.14mm, TI Recommended"
  oval 0.6x0.24 smd: 1(-1.65,0.75) 2(-1.65,0.25) 3(-1.65,-0.25) 4(-1.65,-0.75) 9(1.65,-0.75) 10(1.65,-0.25) 11(1.65,0.25) 12(1.65,0.75)
  oval 0.24x0.6 smd: 5(-0.75,-1.65) 6(-0.25,-1.65) 7(0.25,-1.65) 8(0.75,-1.65) 13(0.75,1.65) 14(0.25,1.65) 15(-0.25,1.65) 16(-0.75,1.65)
  rect 2.14x2.14 smd paste-1.07: 17(0,0)
  silkscreen extent -1.95,-1.95 1.95,1.95, body extent -1.8,-1.8 1.8,1.8, height 1.01
SMB [mil] "Molded Diode, 2-Leads, Body 5.4x3.6mm, IPC Medium Density, based on OnSemi component dimensions"
  rect 85x107.99 smd: 1(-87.01,0) 2(87.01,0)
  silkscreen extent -155,-82 125,82, body extent -106,-71 106,71, height 91
SNT-100-BK-G [mil] "Samtec STEP model"
  round 1 on Mech3: 0(0,0)
  body extent -100,-50 100,50, height 344
SOD-80 [mm] "VISHAY"
  rect 1.25x2 smd: 1(-1.875,0) 2(1.875,0)
  silkscreen extent -0.76,-0.8 0.76,0.84, body extent -1.85,-0.81 1.85,0.81, height 1.62
SOD-123 [mm] "On Semi recommended land pattern"
  rect 0.915x1.22 smd: 1(-1.637,0) 2(1.637,0)
  silkscreen extent -2.74,-1.17 2.03,1.17, body extent -1.93,-0.9 1.93,0.9, height 1.35
SOD-323F [mm] "NXP recommended land pattern"
  rect 0.6x0.6 smd paste-0.05: 1(-1.1,0) 2(1.1,0)
  silkscreen extent -2.06,-0.86 1.53,0.86, body extent -1.35,-0.67 1.35,0.68, height 0.79
SOD-523F [mm] "COMCHIP"
  rect 0.6x0.8 smd paste-0.05: 1(-0.85,0) 2(0.85,0)
  silkscreen extent -1.93,-0.87 1.1,0.87, body extent -0.9,-0.5 0.9,0.5, height 0.85
SOT1061 [mm] "NXP SEMICONDUCTOR (HUSON3)"
  rect 0.5x0.4 smd mask+0.05: 1(-0.8,0.65) 2(-0.8,-0.65)
  rect 1.1x1.6 smd mask+0.05: 3(0.25,0)
  Layer 1 - Top Layer region: 1.05,-0.2 1.05,0.2 0.7,0.2 0.7,-0.2
  silkscreen extent -1.25,-1.15 1.15,1.45, body extent -1.05,-1.05 1.05,1.05, height 0.66
SW_SKRKAEE010 [mm] "Alps recommended land pattern"
  rect 0.8x2 smd: 1(-2.1,0) 2(2.1,0)
  body extent -2.4,-1.45 2.4,1.45, height 1.96
TERM_BLK_ED555-2DS [mil]
  rect 100x100 hole 50: 1(0,0)
  round 100 hole 50: 2(138,0)
  silkscreen extent -93,-161 215,113, body extent -69,-150 207,106, height 323
TI_Horizontal_Overlay_Small [mil]
  silkscreen extent -545,-68 545,67
Wurth_750314445 [mm] "WURTH"
  rect 1.17x1.91 smd: 1(-3.735,4.065) 2(-1.245,4.065) 3(1.245,4.065) 4(3.735,4.065) 5(3.735,-4.065) 6(1.245,-4.065) 7(-1.245,-4.065) 8(-3.735,-4.065)
  silkscreen extent -5,-4.05 4.9,4.15, body extent -4.92,-4.58 4.9,4.58, height 10.1

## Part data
C1: library part GRM155R61A103KA01D
C2 C3 C4 C9 C10: "CAP, CERM, 10uF, 10V, +/-10%, X7R, 0805"
C5: library part GRM21BR72A474KA73L
C6: library part GRM188R72A103KA01D
C7: library part C1005X5R1C225K050BC
C8 C12 C15: library part GRM21BR71A106KE51L
C11 C52: "CAP, CERM, 0.1uF, 10V, +/-10%, X5R, 0402"
C13 C19 C20 C21 C22: library part GRM155R61A105KE15D
C14: library part GRM31CR61A226KE19L
C16 C17: library part GRM155R61A475M
C18: "CAP, CERM, 560pF, 50V, +/-10%, X7R, 0402"
C23 C37 C43: "CAP, CERM, 1uF, 10V, +/-10%, X5R, 0402"
C24 C25: "CAP, CERM, 2.2uF, 10V, +/-10%, X7R, 0603"
C26: library part GRM155R70J104KA01D
C27 C45 C47 C49: "CAP, CERM, 0.1uF, 6.3V, +/-10%, X7R, 0402"
C28 C29: "CAP, CERM, 0.1uF, 16V, +/-10%, X7R, 0402"
C30 C33: "CAP, CERM, 1000pF, 16V, +/-10%, X7R, 0402"
C31: "CAP, CERM, 0.1uF, 100V, +/-5%, X7R, 1206"
C32: "CAP, CERM, 1uF, 100V, +/-10%, X7R, 1206"
C34 C35 C36 C53: "CAP, CERM, 2200pF, 6.3V, +/-10%, X7R, 0402"
C38 C42: "CAP, CERM, 0.27uF, 6.3V, +/-10%, X5R, 0402"
C39 C40: "CAP, CERM, 0.22uF, 6.3V, +/-10%, X5R, 0402"
C41: "CAP, CERM, 4.7uF, 6.3V, +/-10%, X5R, 0603"
C44: "CAP, CERM, 0.47uF, 6.3V, +/-10%, X7R, 0603"
C46 C48 C50: "CAP, CERM, 10uF, 6.3V, +/-20%, X5R, 0402"
C51: "CAP, CERM, 3.3uF, 10V, +/-10%, X5R, 0603"
D1 D5: "Diode, Schottky, 100V, 0.25A, SOD-323F"
D2 D4: "Diode, Switching, 90V, 0.1A, SOD-523F"
D3: "Diode, TVS, Bi, 39V, 600W, SMB"
D6 D7: "Diode, Fast Rectifier, 75V, 0.2A, 3.7x1.6x1.6mm"
D8: "Diode, Zener, 3.9V, 500mW, SOD-123"
D9: "TVS DIODE 3.3VWM 7.8VC SOD923"
FID1 FID2 FID3 FID4 FID5 FID6: "Fiducial mark.  There is nothing to buy or mount."
H1 H2 H3 H4: "Machine Screw, Round, #4-40 x 1/4, Nylon, Philips panhead"
H5 H6 H7 H8: "Standoff, Hex, 0.5\"L #4-40 Nylon"
J1 J3: "Terminal Block, 6A, 3.5mm Pitch, 2-Pos, TH"
J2: "Header, 100mil, 2x1, Tin plated, TH"
J6 J7: "Header, 100mil, 3x1, Tin plated, TH"
J8: "Header (shrouded), 100 mil, 7x2, Gold plated, TH"
L1 L3: "Inductor, Wirewound, Ferrite, 47uH, 0.11A, 1.235 ohm, SMD"
L2: "Coupled inductor, 470uH, 0.1A, 0.35 ohm, +/-30%, SMD"
L4: "Inductor, Wirewound, Ferrite, 33uH, 0.13A, 0.7 ohm, SMD"
L5: "Ferrite Bead, 600 ohm @ 100MHz, 0.2A, 0603"
Logo1: library part TI_Logo, "Texas Instrument Corporate Signature"
Q1: library part "BC56-16PA,115, NXP Semiconductor", "Transistor, NPN, 80V, 1A, SOT1061"
R1: "RES, 200 ohm, 1%, 0.25W, 1206"
R2 R9: "RES, 0 ohm, 5%, 0.125W, 0805"
R3: "RES, 100k ohm, 1%, 0.063W, 0402"
R4: library part CRCW0402698KFKED
R5: library part CRCW0402200RFKED
R6 R7: "RES, 200 ohm, 1%, 0.063W, 0402"
R8: library part CRCW0402237KFKED
R10 R13: library part CRCW0402499KFKED
R11: library part CRCW04021K00FKED
R12: "RES, 0 ohm, 5%, 0.1W, 0603"
R14: library part CRCW040210R0FKED
R15 R17 R18 R21 R22 R28 R29 R38 R39 R40 R42: "RES, 10.0 ohm, 1%, 0.1W, 0603"
R19: library part CRCW04020000Z0ED
R20: "RES, 0 ohm, 5%, 0.063W, 0402"
R23: "RES, 100 ohm, 0.1%, 0.1W, 0603"
R24 R27: "RES, 40.2 ohm, 1%, 0.063W, 0402"
R25: "RES, 20.0 ohm, 1%, 0.1W, 0603"
R26: "RES, 0 ohm, 5%, 0.25W, 1206"
R30 R37: "RES, 2.00Meg ohm, 1%, 0.063W, 0402"
R31: "RES, 3.24k ohm, 0.1%, 0.333W, 1206"
R32 R36: "RES, 1.00k ohm, 1%, 0.063W, 0402"
R33 R34 R35: "RES, 47 ohm, 5%, 0.063W, 0402"
R41 R46: "RES, 1.0Meg ohm, 5%, 0.063W, 0402"
R43: "RES, 47k ohm, 5%, 0.063W, 0402"
R44: "RES, 2.00k ohm, 1%, 0.063W, 0402"
S1 S2: "Switch, Push Button, SMD"
SH-J2 SH-J3: "Shunt, 100mil, Gold plated, Black"
T1: "Transformer, 3mH, SMT"
T3: "Transformer_400uH, SMT"
TC1: "Temperature Sensor, 100 ohm, 1%, 1206"
TP1 TP3 TP8 TP9 TP10: "Test Point, Miniature, Red, TH"
TP2 TP6 TP11: "Test Point, Miniature, White, TH"
TP4 TP5 TP7: "Test Point, Miniature, Black, TH"
U1: "60-V, 5-µA IQ, 100-mA, Low-Dropout Voltage Regulator with Enable and Power-Good, DRB0008A"
U2: "UNREGULATED 60-mA CHARGE PUMP VOLTAGE INVERTER, DBV0005A"
U3 U4: "Low Noise, High-Bandwidth PSRR Low-Dropout 150mA Linear Regulator, DSE0006A"
U5: "Single-Wire 16-bit DAC for 4-20mA loops, RGH0016A"
U6: "Low-Power, Low-Noise, 24-Bit Analog-to-Digital Converter for Small Signal Sensors, RVA0016A"
U7: "Mixed Signal Microcontroller, RSB0040B"
U8: "QUADRUPLE BUS BUFFER GATE WITH 3-STATE OUTPUTS,  RGY0014A"
ZZ1: library part AssemblyNoteLabel
ZZ2 ZZ3 ZZ4: library part AssemblyNote

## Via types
v1: diameter 20, hole 10, Layer 1 - Top Layer to Layer 4 - Bottom Layer, 147 vias
v2: diameter 19.68, hole 7.87, Layer 1 - Top Layer to Layer 4 - Bottom Layer, 22 vias

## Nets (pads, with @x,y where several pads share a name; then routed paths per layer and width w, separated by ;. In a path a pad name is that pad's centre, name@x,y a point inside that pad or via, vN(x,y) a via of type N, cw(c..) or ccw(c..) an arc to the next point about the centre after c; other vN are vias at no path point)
3V3: C22.1 R21.2 R22.2 TP9.1 U3.1 | length 1831.5
  Layer 1 - Top Layer w20: R21.2@1563.5,1340 1560,1343.5 1560,1390 v1(1605,1390)
  Layer 3 - Inner Layer w30: TP9.1@250,975 405,1130 918.54,1130 1028.54,1240 1455,1240 v1(1605,1390)
  Layer 4 - Bottom Layer w30: TP9.1@250,975 382.32,1107.32 C22.1@382.32,1128.38
4V7: C1.1 C7.1 L2.2 R2.1 R4.2 R17.1 TP3.1 U1.1 | length 279.3
  Layer 4 - Bottom Layer w20: R17.1@323.5,1330 323.5,1338.5 TP3.1@410,1425 420,1425 485,1490 485,1531.38 C1.1@481.38,1535
AIN0: C38.2 C41.1 R32.2 U6.9 | length 176.9
  Layer 1 - Top Layer w12: U6.9@626.25,480.47 649.07,480.47 681.05,448.5 C41.1@685,448.5
  Layer 1 - Top Layer w20: C41.1@685,448.5 693.5,440 R32.2@741.38,440 C38.2@741.38,485
AIN1: C41.2 C42.1 R36.2 U6.8 | length 239.7
  Layer 1 - Top Layer w12: U6.8@599.53,453.75 599.53,418.47 613,405
  Layer 1 - Top Layer w20: 613,405 632.5,385.5 C41.2@685,385.5 694.5,395 R36.2@741.38,395 C42.1@741.38,350
AIN2: C37.2 C43.1 R31.1 TC1.2 U6.5 U6.7 | length 664.7
  Layer 4 - Bottom Layer w12: v1(560,390) 580,370 725,370 811.38,283.62 C43.1@855,283.62 871.38,300 985,300 1032.09,252.91 TC1.2@1032.09,245
  Layer 4 - Bottom Layer w20: R31.1@485,437.91 543.46,437.91 C37.2@561.38,420 560,418.62 v1(560,390)
AIN3: C43.2 TC1.1 U6.4 | length 579.2
  Layer 1 - Top Layer w12: 505.04,445.04 U6.4@505.04,479
  Layer 1 - Top Layer w20: v1(505,370) 505.04,445.04
  Layer 4 - Bottom Layer w12: v1(505,370) 540,335 720,335 816.65,238.35 911.26,238.35 TC1.1@917.91,245
BSL_RX: J8.14 U7.35 | length 1610.7
  Layer 1 - Top Layer w8: U7.35@1027.87,781.46 1027.87,802.87 v1(1045,820)
  Layer 3 - Inner Layer w8: v1(1045,820) 1160,820 1240,740 1738.28,740 1790,791.72 1790,993.28 1866.72,1070 1975,1070 2055,1150 2110,1150 2130,1170 2130,1250 J8.14@2080,1300
BSL_TX: J8.12 U7.36 | length 1452.9
  Layer 1 - Top Layer w8: U7.36@1012.13,781.46 v1@1012.13,821
  Layer 3 - Inner Layer w8: v1@1012.13,821 1036.13,845 1165,845 1250,760 1730,760 1770,800 1770,1001.57 1858.43,1090 1970,1090 J8.12@2080,1200
  other v1: 1012,821
DIN_ADC: R35.2 U7.3 | length 352.8
  Layer 1 - Top Layer w8: R35.2@600,693.62 601.38,695 v1(630,695) ; v1(820,675) 869.37,724.37 U7.3@923.54,724.37
  Layer 3 - Inner Layer w8: v1(630,695) 650,675 v1(820,675)
DOUT_ADC: U6.13 U7.4 | length 390.8
  Layer 1 - Top Layer w8: U6.13@599.53,574.96 599.53,594.53 v1(610,605) ; v1(860,675) 893.62,708.62 U7.4@923.54,708.62
  Layer 3 - Inner Layer w8: v1(610,605) 660,605 700,645 830,645 v1(860,675)
ERRLVL: J7.2 U5.8 | length 584.4
  Layer 1 - Top Layer w8: v1(1380,1295) 1430,1245 1870,1245 J7.2@1875,1250
  Layer 4 - Bottom Layer w8: v1(1380,1295) 1394.8,1280.2 U5.8@1440.47,1280.2
GND: C5.2 C7.2 C11.2 C22.2 C24.2 C26.2 C28.2 C29.2 C34.2 C35.2 C36.2 D9.1 J7.3 L2.1 R8.1 R9.1 R25.1 TP4.1 U1.4 U1.9 U3.2 U5.1 U5.2 U5.10 U5.17 | length 757.7
  Layer 1 - Top Layer w12: C29.2@1510,1396.38 C29.2@1511.34,1395.04
  Layer 1 - Top Layer w20: v2(1470,1313.66) 1498.66,1285 C28.2@1571.38,1285 ; v2(1511.34,1355) C29.2@1511.34,1395.04
  Layer 4 - Bottom Layer w8: C22.2@335.08,1128.38 354.7,1148 U3.2@354.7,1177.76 ; U5.10@1395.2,1345.16 U5.17@1460.16,1345.16 ; U5.17@1479.84,1364.84 U5.2@1544.8,1364.84 ; U5.17@1499.53,1384.53 U5.1@1544.8,1384.53
  Layer 4 - Bottom Layer w20: v1@225,1129.76 C26.2@283.7,1129.76 285.08,1128.38 C22.2@335.08,1128.38 ; v1(465,1300) 496.5,1268.5 C24.2@496.5,1225 ; v1(495,1360) R8.1@495,1396.38 ; v2(636.17,1440.13) 636.17,1459.79 C11.2@651.38,1475 ; D9.1@1295,1456.54 1307.09,1468.62 C34.2@1340,1468.62 1371.38,1468.62 v1(1380,1460)
  other v1: 225,1130 1405,1595
  other v2: 1428.66,1355 1470,1355 1470,1396.34 596.8,1400.76 636.17,1400.76 596.8,1440.13
GND2: C9.2 C10.2 C15.2 C16.2 C17.2 C18.2 L3.2 R6.1 R7.1 R13.1 TP7.1 U2.4
  other v1: 975,1100 1005,1100
ISO1: C30.1 T3.6 U8.5 | length 647
  Layer 4 - Bottom Layer w8: U8.5@834.96,830.31 940.31,830.31 955,845 1305,845 1345,805 C30.1@1360,805 1427.6,805 T3.6@1450,827.4
ISO2: R24.1 U8.3 | length 565.8
  Layer 4 - Bottom Layer w8: U8.3@834.96,869.68 860,869.68 875.32,885 956,885 980,861 1278.32,861 1337.32,920 R24.1@1360,920
ISO3: T3.4 U8.8 | length 1598.2
  Layer 3 - Inner Layer w8: v1(716,785) 686.04,815 560,815 530,845 530,945 610,1025 1000,1025 1150,875 v1(1650,875)
  Layer 4 - Bottom Layer w8: v1(716,785) U8.8@740.48,785.04 ; T3.4@1650,827.4 v1(1650,875)
ISO3V3: C23.1 J6.2 R28.2 R29.2 R30.2 R38.2 R39.2 R40.2 R41.2 R42.1 R43.2 R46.2 TP10.1 U4.1 | length 4213.2
  Layer 1 - Top Layer w20: v1(705,260) R30.2@741.38,260 ; R43.2@1233.62,760 1251.5,742.13 R39.2@1251.5,705 1251.5,656.5 TP10.1@1210,615 1245,580 1310,580 1333.62,556.38 C23.1@1333.62,545 ; R41.2@1583.62,250 v1(1630,250) ; v1(1735,250) R46.2@1781.38,250
  Layer 1 - Top Layer w30: R38.2@880,856.5 v1(928.5,856.5)
  Layer 3 - Inner Layer w30: v1(565,875) 565,915 640,990 891.46,990 928.5,952.95 v1(928.5,856.5) 928.5,811.5 958.54,781.46 1083.39,781.46 1115,749.84 1115,625 1125,615 TP10.1@1210,615 ; v1(845,540) 660,355 660,290 690,260 v1(705,260) 753.19,260 773.19,280 1280,280 1365,365 v1@1365,530
  Layer 4 - Bottom Layer w20: v1(565,875) 565,906.5 R42.1@588.5,930 ; R29.2@791.5,480 R28.2@791.5,540 v1(845,540) ; R40.2@1131.5,595 1151.5,615 TP10.1@1210,615
  Layer 4 - Bottom Layer w30: v1@1365,530 1365,500 1365,470 1365,435 1550,250 v1(1630,250) v1(1735,250) 1950,465 1950,675 J6.2@1875,750
  other v1: 1367,465 1367,495 1367,525
ISO_RX: R44.2 U7.12 U8.9 U8.11 | length 605.6
  Layer 1 - Top Layer w8: v1(670,840) 700,840 750,790 R44.2@750,785 v1(750,755) ; v1(945,550) 947,550 964.88,567.88 U7.12@964.88,588.54
  Layer 3 - Inner Layer w8: v1(750,755) 820,755 915,660 915,580 v1(945,550)
  Layer 4 - Bottom Layer w8: U8.9@705.04,810.63 684.37,810.63 670,825 v1(670,840) 680,850 U8.11@705.04,850
ISO_TX: U7.13 U8.12 | length 736.1
  Layer 1 - Top Layer w8: v1(980,550) 980.63,550.63 U7.13@980.63,588.54
  Layer 3 - Inner Layer w8: v1(635,860) 685,910 805,910 860,855 860,743.62 930.5,673.12 930.5,599.5 v1(980,550)
  Layer 4 - Bottom Layer w8: v1(635,860) 644.68,869.68 U8.12@705.04,869.68
LOOP_M: C31.2 C32.2 D4.2 D5.2 R26.2
  other v1: 1258,1319 1258,1350 1258,1380 1258,1410
LOOP_P: D1.1 D2.1 R1.1 R23.2
N_ISO_TX_EN: U7.14 U8.1 U8.13 | length 912.4
  Layer 1 - Top Layer w8: U7.14@996.38,588.54 996.38,568.62 v1(1015,550)
  Layer 3 - Inner Layer w8: v1(600,875) 675,950 800,950 880,870 880,810 990,700 990,575 v1(1015,550)
  Layer 4 - Bottom Layer w8: v1(600,875) 614.37,889.37 U8.13@705.04,889.37 ; U8.1@799.53,914.96 v1(799.53,950)
NCS_ADC: R33.2 U7.1 | length 502.9
  Layer 1 - Top Layer w8: R33.2@515,693.62 v1(515,740) ; v1(765,725) 795.87,755.87 U7.1@923.54,755.87
  Layer 3 - Inner Layer w8: v1(515,740) 540,765 650,765 660,775 685,775 735,725 v1(765,725)
NDRDY_ADC: U6.12 U7.5 | length 399.2
  Layer 1 - Top Layer w8: U6.12@634.96,539.53 634.96,574.96 v1(640,580) ; v1(890,635) 890,680 902.87,692.87 U7.5@923.54,692.87
  Layer 3 - Inner Layer w8: v1(640,580) 805,580 860,635 v1(890,635)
